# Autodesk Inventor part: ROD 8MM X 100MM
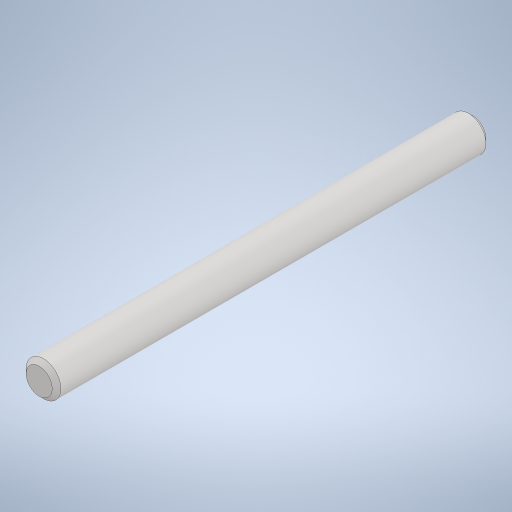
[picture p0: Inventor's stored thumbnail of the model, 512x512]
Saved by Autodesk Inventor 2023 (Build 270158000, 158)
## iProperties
Created: 2025-07
Part Number: ROD 8MM X 100MM
Material: Generic
Document SubType Name: Modeling
Designer: erjon
Density: 1 g/cm^3
Appearance: Default
Author: erjon
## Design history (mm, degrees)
feature "Base1"
body "Solid1"
